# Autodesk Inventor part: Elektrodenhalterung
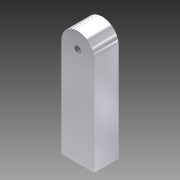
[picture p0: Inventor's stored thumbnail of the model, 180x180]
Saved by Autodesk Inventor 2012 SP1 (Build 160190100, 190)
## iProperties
Created: 2012-10
Part Number: Elektrodenhalterung
Material: Default
Document SubType Name: Modeling
Designer: Dominic Mähling
Density: 1 g/cm^3
Author: Dominic Mähling
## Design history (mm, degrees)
derived "Funkenstrecke master.ipt"
feature "Elektrodenhalterung::Funkenstrecke master.ipt" dims "d0" = 10
tag "Bezeichnung1"
node "Volumenkörper1"
